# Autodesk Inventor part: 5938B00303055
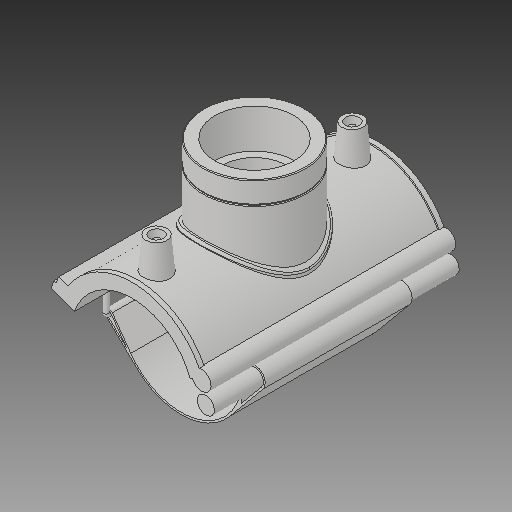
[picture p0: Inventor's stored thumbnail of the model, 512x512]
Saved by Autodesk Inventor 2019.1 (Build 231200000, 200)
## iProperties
Created: 2017-07
Part Number: 5938B00303055
Material: Generic
Description: PLASSON TRANSITION SADDLE 3''IPS x 2"NPT
Document SubType Name: Modeling
Designer: KIM
Density: 1 g/cm^3
Appearance: Default
Author: KIM
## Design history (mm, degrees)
derived "5938B.ipt"
feature "Solid1::5938B.ipt"
tag "TaggingFeature1"
body "Solid1"
other parameters: "d_" = 88.7, "B_" = 136.652, "H_" = 46.736, "L_" = 176.022, "d_t" = 6, "G_" = 56.656, "d148" = 1.3305, "d160" = 1.3305, "d169" = 1.3305, "d192" = 3.548, "d0" = 88.7, "d1" = 106.44, "d2" = 341.63, "d3" = 22.175, "d4" = 176.022, "d5" = 0, "d40" = 55.3488, "d41" = 79.3184, "d43" = 0, "d45" = 0, "d47" = 99.956, "d48" = 73.6528, "d50" = 0, "d78" = 75.22, "d79" = 15, "d80" = 70.4088, "d82" = 5 deg, "d84" = 4, "d85" = 14, "d86" = 0, "d87" = 3, "d88" = 0, "d96" = 108.5688, "d97" = 3.52044, "d98" = 0, "d102" = 1.69968, "d103" = 56.656, "d104" = 28.0416, "d105" = 0, "d106" = 45.3248, "d108" = 0, "d109" = -15.57867, "d111" = 0.5, "d112" = 0.5, "d113" = 0, "d114" = 0.5, "d117" = 0.56656, "d120" = 140 deg, "d121" = 24.228, "d122" = 20 deg, "d123" = 425.76, "d124" = 63.864, "d126" = 0, "d143" = 91.361, "d145" = 13.64615, "d149" = 1.3305, "d150" = 15.01077, "d153" = 176.022, "d154" = 0, "d156" = 53.22, "d157" = 160 deg, "d159" = 3.548, "d161" = 1.3305, "d162" = 105.6132, "d163" = 0, "d164" = 44.35, "d167" = 8.87, "d168" = 51.92195, "d170" = 1.3305, "d172" = 0, "d173" = 1, "d175" = 44.35, "d176" = 20 deg, "d177" = 6.209, "d178" = 17.74, "d180" = 0, "d183" = 7.096, "d184" = 4.9672, "d185" = 57.20715, "d186" = 57.20715, "d187" = 53.22, "d188" = 5.322, "d189" = 6.209, "d190" = 0, "d191" = 63.864, "d193" = 3.548, "d194" = 1.81835, "d195" = 90 deg, "d197" = 0, "d199" = 0
